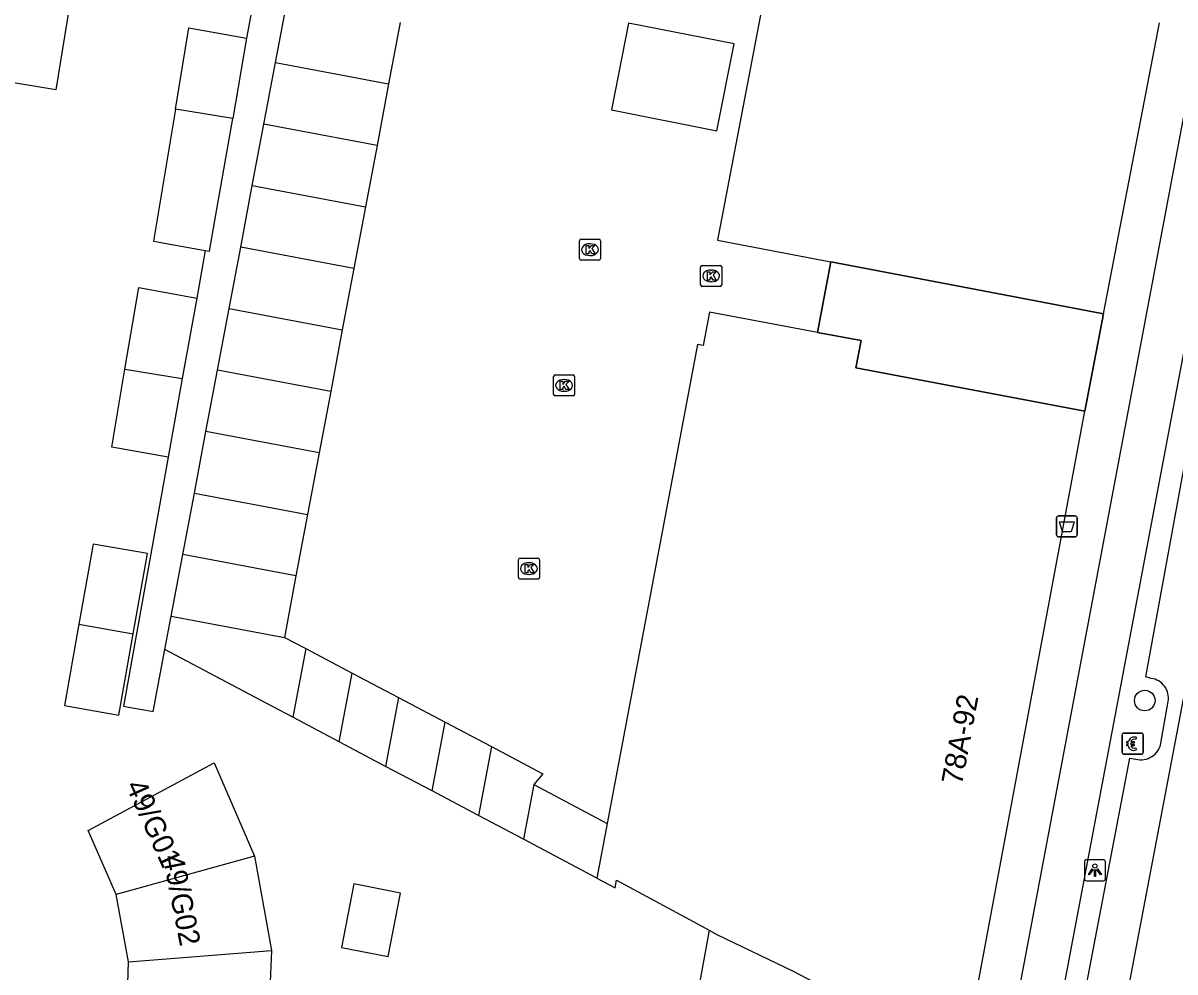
# Model space of a CAD drawing. Extents: x 161402 to 161933, y 381650 to 382313.
# Drawn here: x 161820.7 to 161875.5, y 381837.1 to 381882.3 of the extents above; entities that cross this region are included whole.
import ezdxf

# ---------------------------------------------------------------- set-up
doc = ezdxf.new("R2010")
doc.units = 0
for name, color, linetype in [('IMGEO_Afvalbak', 7, 'Continuous'), ('IMGEO_Betaalautomaat', 7, 'Continuous'), ('IMGEO_Boom', 7, 'Continuous'), ('IMGEO_Fietspad_gesloten', 7, 'Continuous'), ('IMGEO_Kolk', 7, 'Continuous'), ('IMGEO_Lichtpunt', 7, 'Continuous'), ('IMGEO_Pand', 7, 'Continuous'), ('IMGEO_Pand_nummerreeks', 7, 'Continuous'), ('IMGEO_Pand_overbouw', 7, 'Continuous'), ('IMGEO_Parkeervlak_open', 7, 'Continuous'), ('IMGEO_Rijbaan_lokaal_gesloten', 7, 'Continuous'), ('IMGEO_Rijbaan_lokaal_open', 7, 'Continuous'), ('IMGEO_Voetpad_open', 7, 'Continuous')]:
    doc.layers.add(name, color=color, linetype=linetype)

msp = doc.modelspace()

# ---------------------------------------------------------------- linework, layer by layer
at = {"layer": 'IMGEO_Afvalbak'}
for p, q in [((161869.879, 381857.941), (161869.879, 381858.741)), ((161869.879, 381858.741), (161869.879, 381857.941)), ((161869.979, 381858.841), (161870.769, 381858.841)), ((161870.769, 381858.841), (161869.979, 381858.841)), ((161870.869, 381858.741), (161870.869, 381857.941)), ((161870.869, 381857.941), (161870.869, 381858.741)), ((161870.769, 381857.841), (161869.979, 381857.841)), ((161869.979, 381857.841), (161870.769, 381857.841))]:
    msp.add_line(p, q, dxfattribs=at)
msp.add_lwpolyline([(161870.022, 381858.555), (161870.726, 381858.555), (161870.577, 381858.085), (161870.171, 381858.085), (161870.022, 381858.555)], dxfattribs=at)
for centre, start, end in [((161869.979, 381858.741), 90, 180), ((161869.979, 381858.741), 90, 180), ((161870.769, 381858.741), 0, 90), ((161870.769, 381858.741), 360, 90), ((161869.979, 381857.941), 180, 270), ((161869.979, 381857.941), 180, 270), ((161870.769, 381857.941), 270, 0), ((161870.769, 381857.941), 270, 0)]:
    msp.add_arc(centre, 0.1, start, end, dxfattribs=at)
at = {"layer": 'IMGEO_Betaalautomaat'}
for p, q in [((161873.009, 381847.567), (161873.009, 381848.408)), ((161873.009, 381848.408), (161873.009, 381847.567)), ((161873.084, 381848.491), (161873.925, 381848.491)), ((161873.925, 381848.491), (161873.084, 381848.491)), ((161874.008, 381848.417), (161874.008, 381847.576)), ((161874.008, 381847.576), (161874.008, 381848.417)), ((161873.292, 381847.955), (161873.292, 381848.023)), ((161873.413, 381848.023), (161873.413, 381847.955)), ((161873.671, 381848.296), (161873.654, 381848.196)), ((161873.658, 381847.79), (161873.68, 381847.703)), ((161873.934, 381847.492), (161873.093, 381847.492)), ((161873.093, 381847.492), (161873.934, 381847.492))]:
    msp.add_line(p, q, dxfattribs=at)
for points in [[(161873.292, 381848.023), (161873.223, 381848.023), (161873.223, 381848.092), (161873.302, 381848.092)], [(161873.297, 381847.886), (161873.223, 381847.886), (161873.223, 381847.955), (161873.292, 381847.955)], [(161873.424, 381848.092), (161873.571, 381848.092), (161873.571, 381848.023), (161873.413, 381848.023)], [(161873.413, 381847.955), (161873.571, 381847.955), (161873.571, 381847.886), (161873.427, 381847.886)]]:
    msp.add_lwpolyline(points, dxfattribs=at)
for centre, radius, start, end in [((161873.087, 381848.414), 0.0779, 92.4484, 184.2845), ((161873.087, 381848.414), 0.0779, 92.4484, 184.2845), ((161873.585, 381848.016), 0.293, 73.014, 165.0139), ((161873.931, 381848.414), 0.0779, 2.4484, 94.2845), ((161873.931, 381848.414), 0.0779, 2.4484, 94.2845), ((161873.558, 381847.941), 0.267, 191.8096, 297.0389), ((161873.591, 381848.029), 0.179, 69.3236, 159.5683), ((161873.591, 381847.956), 0.179, 202.7625, 291.8693), ((161873.087, 381847.57), 0.0779, 182.4484, 274.2845), ((161873.087, 381847.57), 0.0779, 182.4484, 274.2845), ((161873.931, 381847.57), 0.0779, 272.4484, 4.2845), ((161873.931, 381847.57), 0.0779, 272.4484, 4.2845)]:
    msp.add_arc(centre, radius, start, end, dxfattribs=at)
at = {"layer": 'IMGEO_Boom'}
msp.add_circle((161874.082, 381850.044), 0.489, dxfattribs=at)
at = {"layer": 'IMGEO_Fietspad_gesloten'}
for points in [[(161869.899, 381834.602), (161881.54, 381896.271), (161882.623, 381902.093), (161888.398, 381933.147), (161890.059, 381942.083), (161900.83, 382000), (161908.061, 382038.88), (161912.039, 382060.567)], [(161886.669, 381935.154), (161880.56, 381902.497), (161879.486, 381896.758), (161857.65, 381780.798), (161851.928, 381750), (161842.232, 381697.819)]]:
    msp.add_lwpolyline(points, dxfattribs=at)
at = {"layer": 'IMGEO_Kolk'}
for p, q in [((161847.181, 381871.093), (161847.181, 381871.945)), ((161847.256, 381872.019), (161848.108, 381872.019)), ((161848.182, 381871.945), (161848.182, 381871.093)), ((161847.669, 381871.799), (161847.694, 381871.799)), ((161848.108, 381871.019), (161847.256, 381871.019)), ((161847.692, 381871.239), (161847.667, 381871.239)), ((161852.948, 381869.843), (161852.948, 381870.695)), ((161853.023, 381870.769), (161853.875, 381870.769)), ((161853.436, 381870.549), (161853.461, 381870.549)), ((161853.949, 381870.695), (161853.949, 381869.843)), ((161853.875, 381869.769), (161853.023, 381869.769)), ((161853.459, 381869.989), (161853.434, 381869.989)), ((161845.947, 381864.629), (161845.947, 381865.481)), ((161846.022, 381865.555), (161846.874, 381865.555)), ((161846.435, 381865.335), (161846.46, 381865.335)), ((161846.948, 381865.481), (161846.948, 381864.629)), ((161846.458, 381864.775), (161846.433, 381864.775)), ((161846.874, 381864.555), (161846.022, 381864.555)), ((161844.277, 381855.903), (161844.277, 381856.755)), ((161844.352, 381856.829), (161845.204, 381856.829)), ((161844.765, 381856.609), (161844.79, 381856.609)), ((161845.278, 381856.755), (161845.278, 381855.903)), ((161844.788, 381856.049), (161844.763, 381856.049)), ((161845.204, 381855.829), (161844.352, 381855.829))]:
    msp.add_line(p, q, dxfattribs=at)
for points in [[(161847.181, 381871.093), (161847.181, 381871.945)], [(161847.256, 381872.019), (161848.108, 381872.019)], [(161848.182, 381871.945), (161848.182, 381871.093)], [(161847.502, 381871.719), (161847.625, 381871.719), (161847.625, 381871.568), (161847.755, 381871.719), (161847.919, 381871.719), (161847.773, 381871.568), (161847.926, 381871.319), (161847.774, 381871.319), (161847.689, 381871.483), (161847.625, 381871.416), (161847.625, 381871.319), (161847.502, 381871.319), (161847.502, 381871.719)], [(161848.108, 381871.019), (161847.256, 381871.019)], [(161852.948, 381869.843), (161852.948, 381870.695)], [(161853.023, 381870.769), (161853.875, 381870.769)], [(161853.269, 381870.469), (161853.392, 381870.469), (161853.392, 381870.318), (161853.522, 381870.469), (161853.686, 381870.469), (161853.54, 381870.318), (161853.693, 381870.069), (161853.541, 381870.069), (161853.456, 381870.233), (161853.392, 381870.166), (161853.392, 381870.069), (161853.269, 381870.069), (161853.269, 381870.469)], [(161853.949, 381870.695), (161853.949, 381869.843)], [(161853.875, 381869.769), (161853.023, 381869.769)], [(161845.947, 381864.629), (161845.947, 381865.481)], [(161846.022, 381865.555), (161846.874, 381865.555)], [(161846.948, 381865.481), (161846.948, 381864.629)], [(161846.268, 381865.255), (161846.391, 381865.255), (161846.391, 381865.104), (161846.521, 381865.255), (161846.685, 381865.255), (161846.539, 381865.104), (161846.692, 381864.855), (161846.54, 381864.855), (161846.455, 381865.019), (161846.391, 381864.952), (161846.391, 381864.855), (161846.268, 381864.855), (161846.268, 381865.255)], [(161846.874, 381864.555), (161846.022, 381864.555)], [(161844.277, 381855.903), (161844.277, 381856.755)], [(161844.352, 381856.829), (161845.204, 381856.829)], [(161844.598, 381856.529), (161844.721, 381856.529), (161844.721, 381856.378), (161844.851, 381856.529), (161845.015, 381856.529), (161844.869, 381856.378), (161845.022, 381856.129), (161844.87, 381856.129), (161844.785, 381856.293), (161844.721, 381856.226), (161844.721, 381856.129), (161844.598, 381856.129), (161844.598, 381856.529)], [(161845.278, 381856.755), (161845.278, 381855.903)], [(161845.204, 381855.829), (161844.352, 381855.829)]]:
    msp.add_lwpolyline(points, dxfattribs=at)
for centre, start, end in [((161847.258, 381871.943), 91.552, 178.448), ((161847.258, 381871.943), 91.552, 178.448), ((161848.106, 381871.943), 1.552, 88.448), ((161848.106, 381871.943), 1.552, 88.448), ((161847.258, 381871.095), 181.552, 268.448), ((161847.258, 381871.095), 181.552, 268.448), ((161848.106, 381871.095), 271.552, 358.448), ((161848.106, 381871.095), 271.552, 358.448), ((161853.025, 381870.693), 91.552, 178.448), ((161853.025, 381870.693), 91.552, 178.448), ((161853.873, 381870.693), 1.552, 88.448), ((161853.873, 381870.693), 1.552, 88.448), ((161853.025, 381869.845), 181.552, 268.448), ((161853.025, 381869.845), 181.552, 268.448), ((161853.873, 381869.845), 271.552, 358.448), ((161853.873, 381869.845), 271.552, 358.448), ((161846.024, 381865.479), 91.552, 178.448), ((161846.024, 381865.479), 91.552, 178.448), ((161846.872, 381865.479), 1.552, 88.448), ((161846.872, 381865.479), 1.552, 88.448), ((161846.024, 381864.631), 181.552, 268.448), ((161846.024, 381864.631), 181.552, 268.448), ((161846.872, 381864.631), 271.552, 358.448), ((161846.872, 381864.631), 271.552, 358.448), ((161844.354, 381856.753), 91.552, 178.448), ((161844.354, 381856.753), 91.552, 178.448), ((161845.202, 381856.753), 1.552, 88.448), ((161845.202, 381856.753), 1.552, 88.448), ((161844.354, 381855.905), 181.552, 268.448), ((161844.354, 381855.905), 181.552, 268.448), ((161845.202, 381855.905), 271.552, 358.448), ((161845.202, 381855.905), 271.552, 358.448)]:
    msp.add_arc(centre, 0.0765, start, end, dxfattribs=at)
for centre, major_axis, ratio, start_param, end_param in [((161847.668, 381871.519), (-0.387, 0.002), 0.722429, 4.712389, 7.853982), ((161847.693, 381871.519), (-0.39, 0.002), 0.717154, 1.570796, 4.712389), ((161853.435, 381870.269), (-0.387, 0.002), 0.722429, 4.712389, 7.853982), ((161853.46, 381870.269), (-0.39, 0.002), 0.717154, 1.570796, 4.712389), ((161846.434, 381865.055), (-0.387, 0.002), 0.722429, 4.712389, 7.853982), ((161846.459, 381865.055), (-0.39, 0.002), 0.717154, 1.570796, 4.712389), ((161844.764, 381856.329), (-0.387, 0.002), 0.722429, 4.712389, 7.853982), ((161844.789, 381856.329), (-0.39, 0.002), 0.717154, 1.570796, 4.712389)]:
    msp.add_ellipse(centre, major_axis=major_axis, ratio=ratio, start_param=start_param, end_param=end_param, dxfattribs=at)
at = {"layer": 'IMGEO_Lichtpunt'}
for p, q in [((161871.211, 381842.366), (161871.211, 381841.559)), ((161871.211, 381842.366), (161871.211, 381841.559)), ((161872.113, 381842.461), (161871.305, 381842.461)), ((161872.113, 381842.461), (161871.305, 381842.461)), ((161872.207, 381841.559), (161872.207, 381842.366)), ((161872.207, 381841.559), (161872.207, 381842.366)), ((161871.305, 381841.465), (161872.113, 381841.465)), ((161871.305, 381841.465), (161872.113, 381841.465))]:
    msp.add_line(p, q, dxfattribs=at)
for points in [[(161871.585, 381842.03), (161871.624, 381842.002), (161871.436, 381841.74), (161871.398, 381841.767), (161871.585, 381842.03)], [(161871.687, 381841.982), (161871.734, 381841.982), (161871.734, 381841.66), (161871.687, 381841.66), (161871.687, 381841.982)], [(161871.797, 381842.002), (161871.835, 381842.029), (161872.022, 381841.767), (161871.983, 381841.739), (161871.797, 381842.002)]]:
    msp.add_lwpolyline(points, dxfattribs=at)
msp.add_circle((161871.71, 381842.164), 0.0994, dxfattribs=at)
for centre, start, end in [((161871.305, 381842.366), 90, 180), ((161871.305, 381842.366), 90, 180), ((161872.113, 381842.366), 0, 90), ((161872.113, 381842.366), 0, 90), ((161871.305, 381841.559), 180, 270), ((161871.305, 381841.559), 180, 270), ((161872.113, 381841.559), 270, 0), ((161872.113, 381841.559), 270, 360)]:
    msp.add_arc(centre, 0.0946, start, end, dxfattribs=at)
at = {"layer": 'IMGEO_Pand'}
for points in [[(161819.956, 381886.143), (161823.31, 381885.597), (161822.259, 381879.139), (161818.905, 381879.685)], [(161832.714, 381880.427), (161833.265, 381883.355)], [(161855.839, 381882.938), (161853.748, 381871.965), (161859.14, 381870.938)], [(161838.65, 381882.342), (161838.099, 381879.413)], [(161872.114, 381868.466), (161874.777, 381882.317)], [(161827.949, 381878.216), (161828.584, 381882.091), (161831.343, 381881.592)], [(161831.343, 381881.592), (161830.679, 381877.773)], [(161832.162, 381877.498), (161832.714, 381880.427)], [(161832.714, 381880.427), (161838.099, 381879.413)], [(161838.099, 381879.413), (161837.548, 381876.485)], [(161827.949, 381878.216), (161826.915, 381871.917), (161829.372, 381871.479)], [(161830.679, 381877.773), (161827.949, 381878.216)], [(161829.372, 381871.479), (161829.578, 381871.442), (161829.832, 381872.901), (161830.679, 381877.773)], [(161831.611, 381874.57), (161832.162, 381877.498)], [(161837.548, 381876.485), (161832.162, 381877.498)], [(161837.548, 381876.485), (161836.997, 381873.556)], [(161831.06, 381871.641), (161831.611, 381874.57)], [(161831.611, 381874.57), (161836.997, 381873.556)], [(161836.997, 381873.556), (161836.446, 381870.628)], [(161830.509, 381868.712), (161831.06, 381871.641)], [(161836.446, 381870.628), (161831.06, 381871.641)], [(161859.14, 381870.938), (161867.064, 381869.428), (161872.114, 381868.466)], [(161836.446, 381870.628), (161835.895, 381867.699)], [(161825.552, 381865.821), (161826.209, 381869.714), (161828.968, 381869.215)], [(161828.968, 381869.215), (161828.277, 381865.379)], [(161829.958, 381865.784), (161830.509, 381868.712)], [(161830.509, 381868.712), (161835.895, 381867.699)], [(161858.508, 381867.582), (161853.371, 381868.549), (161853.071, 381866.952), (161852.795, 381867.004), (161848.503, 381844.194)], [(161835.895, 381867.699), (161835.343, 381864.77)], [(161871.236, 381863.835), (161860.337, 381865.887), (161860.582, 381867.192), (161858.508, 381867.582)], [(161827.603, 381861.635), (161824.926, 381862.113), (161825.552, 381865.821)], [(161825.552, 381865.821), (161828.277, 381865.379)], [(161828.277, 381865.379), (161827.603, 381861.635)], [(161829.407, 381862.855), (161829.958, 381865.784)], [(161835.343, 381864.77), (161829.958, 381865.784)], [(161835.343, 381864.77), (161834.792, 381861.842)], [(161865.464, 381832.9), (161865.498, 381833.078), (161871.236, 381863.835)], [(161828.856, 381859.927), (161829.407, 381862.855)], [(161834.792, 381861.842), (161829.407, 381862.855)], [(161834.792, 381861.842), (161834.241, 381858.913)], [(161828.305, 381856.998), (161828.856, 381859.927)], [(161828.856, 381859.927), (161834.241, 381858.913)], [(161834.241, 381858.913), (161833.69, 381855.985)], [(161825.944, 381853.225), (161826.623, 381857.044), (161824.035, 381857.49), (161823.358, 381853.686)], [(161827.754, 381854.069), (161828.305, 381856.998)], [(161833.69, 381855.985), (161828.305, 381856.998)], [(161833.69, 381855.985), (161833.139, 381853.056)], [(161827.453, 381852.469), (161827.754, 381854.069)], [(161827.754, 381854.069), (161833.139, 381853.056)], [(161823.358, 381853.686), (161822.667, 381849.811), (161825.253, 381849.351), (161825.944, 381853.225)], [(161823.358, 381853.686), (161825.944, 381853.225)], [(161833.139, 381853.056), (161834.153, 381852.521)], [(161833.537, 381849.248), (161832.579, 381849.755), (161827.453, 381852.469)], [(161834.153, 381852.521), (161833.537, 381849.248)], [(161834.153, 381852.521), (161836.363, 381851.354)], [(161835.747, 381848.078), (161836.363, 381851.354)], [(161836.363, 381851.354), (161838.574, 381850.186)], [(161838.574, 381850.186), (161837.957, 381846.908)], [(161838.574, 381850.186), (161840.785, 381849.019)], [(161835.747, 381848.078), (161833.537, 381849.248)], [(161840.167, 381845.738), (161840.785, 381849.019)], [(161840.785, 381849.019), (161842.996, 381847.852)], [(161837.957, 381846.908), (161835.747, 381848.078)], [(161842.996, 381847.852), (161842.378, 381844.568)], [(161842.996, 381847.852), (161845.444, 381846.559), (161845.009, 381846.053)], [(161825.13, 381840.815), (161823.801, 381843.856), (161829.804, 381847.078), (161831.717, 381842.638)], [(161840.167, 381845.738), (161837.957, 381846.908)], [(161842.378, 381844.568), (161840.167, 381845.738)], [(161845.009, 381846.053), (161844.517, 381843.436)], [(161845.009, 381846.053), (161848.503, 381844.194)], [(161844.517, 381843.436), (161842.378, 381844.568)], [(161848.503, 381844.194), (161848.012, 381841.585)], [(161848.012, 381841.585), (161844.517, 381843.436)], [(161831.717, 381842.638), (161825.13, 381840.815)], [(161831.717, 381842.638), (161832.532, 381838.148)], [(161838.073, 381837.848), (161838.666, 381840.875), (161836.451, 381841.309), (161835.858, 381838.282), (161838.073, 381837.848)], [(161848.012, 381841.585), (161848.885, 381841.123), (161848.95, 381841.485), (161852.213, 381839.723), (161853.347, 381839.11)], [(161825.716, 381837.606), (161825.13, 381840.815)], [(161853.347, 381839.11), (161852.346, 381833.514), (161851.141, 381833.729), (161850.676, 381831.127)], [(161853.347, 381839.11), (161853.718, 381838.91), (161857.352, 381837.151), (161865.464, 381832.9)], [(161825.716, 381837.606), (161832.532, 381838.148)], [(161832.532, 381838.148), (161832.326, 381833.3)], [(161825.632, 381834.487), (161825.716, 381837.606)]]:
    msp.add_lwpolyline(points, dxfattribs=at)
at = {"layer": 'IMGEO_Pand_overbouw'}
msp.add_lwpolyline([(161858.508, 381867.582), (161860.582, 381867.192), (161860.337, 381865.887), (161871.236, 381863.835), (161872.114, 381868.466), (161867.064, 381869.428), (161859.14, 381870.938)], close=True, dxfattribs=at)
at = {"layer": 'IMGEO_Parkeervlak_open'}
for points in [[(161853.724, 381877.185), (161854.54, 381881.318), (161849.518, 381882.31), (161848.702, 381878.177), (161853.724, 381877.185)], [(161874.387, 381851.103), (161874.136, 381851.181), (161876.039, 381861.605), (161876.341, 381861.545)], [(161874.852, 381848.012), (161875.194, 381850.001)], [(161872.047, 381836.423), (161871.323, 381836.592), (161873.371, 381847.295), (161873.66, 381847.251)]]:
    msp.add_lwpolyline(points, dxfattribs=at)
for centre, radius, start, end in [((161874.267, 381850.168), 0.942, 349.7715, 82.6595), ((161873.892, 381848.201), 0.978, 256.2704, 348.8398)]:
    msp.add_arc(centre, radius, start, end, dxfattribs=at)
at = {"layer": 'IMGEO_Rijbaan_lokaal_gesloten'}
msp.add_lwpolyline([(161884.15, 381893.504), (161864.093, 381787.863), (161863.613, 381786.178), (161863.081, 381785.029), (161862.376, 381783.945), (161861.521, 381781.789), (161860.529, 381779.475)], dxfattribs=at)
at = {"layer": 'IMGEO_Rijbaan_lokaal_open'}
for points in [[(161858.508, 381867.582), (161859.14, 381870.938)], [(161872.114, 381868.466), (161871.236, 381863.835)]]:
    msp.add_lwpolyline(points, dxfattribs=at)
at = {"layer": 'IMGEO_Voetpad_open'}
for points in [[(161832.263, 381886.525), (161831.343, 381881.592)], [(161829.372, 381871.479), (161828.968, 381869.215)], [(161827.603, 381861.635), (161825.489, 381849.781), (161825.549, 381849.77), (161826.551, 381849.592), (161826.9, 381849.53), (161827.453, 381852.469)]]:
    msp.add_lwpolyline(points, dxfattribs=at)

# ---------------------------------------------------------------- texts
at = {"layer": 'IMGEO_Pand_nummerreeks'}
for s, rotation, p in [('78A-92', 79.3833, (161865.379, 381845.988)), ('49/G01', 294.2277, (161825.57, 381845.997)), ('49/G02', 281.0235, (161827.344, 381842.604))]:
    msp.add_text(s, height=1, rotation=rotation, dxfattribs=at).set_placement(p)

doc.saveas('drawing.dxf')
